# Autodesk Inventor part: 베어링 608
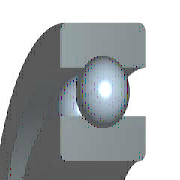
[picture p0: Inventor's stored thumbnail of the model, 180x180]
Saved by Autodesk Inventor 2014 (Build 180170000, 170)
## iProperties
IsCustomPart: 1
Created: 2012-02
Part Number: 베어링 608
Material: 강철, 연강
Description: 깊은 그루브 볼 베어링
Document SubType Name: Modeling
Standard: KS B 2023
Designer: mduedu
Standards Organization: KS
Language: ko-KR
Size Designation: 608 - 8 x 22 x 7
Categories: <MemberInstance><Categories><Category DisplayName="샤프트 부품" InternalName="7f7aeb1f-a693-4053-b835-cee3144e0d98" Mnemonic="SHFT"><Category DisplayName="베어링" Inter
Density: 1 g/cm^3
Appearance: 주황색
Author: mduedu
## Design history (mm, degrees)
sketch "스케치" dims "d0" = 3.64 (= -0.26 x WD + 0.26 x BD)
  geometry: L1 (1.68, 7.5)-(5.32, 7.5); L2 (3.5, 7.5)-(3.5, 5.68); L3 (3.5, 7.5)-(3.5, 9.32); L4 (2.148, 6.282)-(0, 6.282); L5 (0, 4)-(7, 4); L6 (2.148, 8.718)-(0, 8.718); L7 (0, 11)-(7, 11); L8 (7, 4)-(7, 6.282); L9 (4.852, 6.282)-(7, 6.282); L10 (4.852, 8.718)-(7, 8.718); L11 (7, 11)-(7, 8.718); L12 (-1.4, 0)-(8.4, 0) reference; L13 (0, -0.3)-(0, 5.3) reference
  constraints: 22 end point, 4 point on line, 2 collinear, 2 perpendicular, 2 symmetric about line, 1 midpoint, 1 parallel, 14 other
  dimensions: "d9" = 8 diameter of L5 L12 (= WD); "d11" = 22 diameter of L7 L12 (= BD); "d12" = 7 distance between parallel lines of L8 L13 (= KB); "d13" = 12.564 diameter of L9 L12 (= 0.326 x BD + 0.674 x WD)
revolve "본체" stored, may be unused: angle "d6" = 90 deg
revolve "볼" stored, may be unused: angle "d7" = 90 deg
pattern_circular "IDS_ARRAYBALL[SIMPL:T]" dims angle "d3" = 360 deg
body "Solid1"
fillet "모깎기1" dims "d1" = 0.3 (= KRS)
other parameters: "WD" = 8 [user parameter; used in 5 equation terms], "BD" = 22 [user parameter; used in 5 equation terms], "KB" = 7 [user parameter; used in 1 equation term], "KRS" = 0.3 [user parameter; used in 1 equation term], "d4" = 0, "d5" = 0, "d8" = 0, "d14" = 0, "d15" = 0, "BBA" = 0 [user parameter], "BC0" = 1370000 [user parameter], "BC" = 3250000 [user parameter], "BR" = 11 (= 0.5 x BD) [user parameter], "WR" = 4 (= 0.5 x WD) [user parameter]
